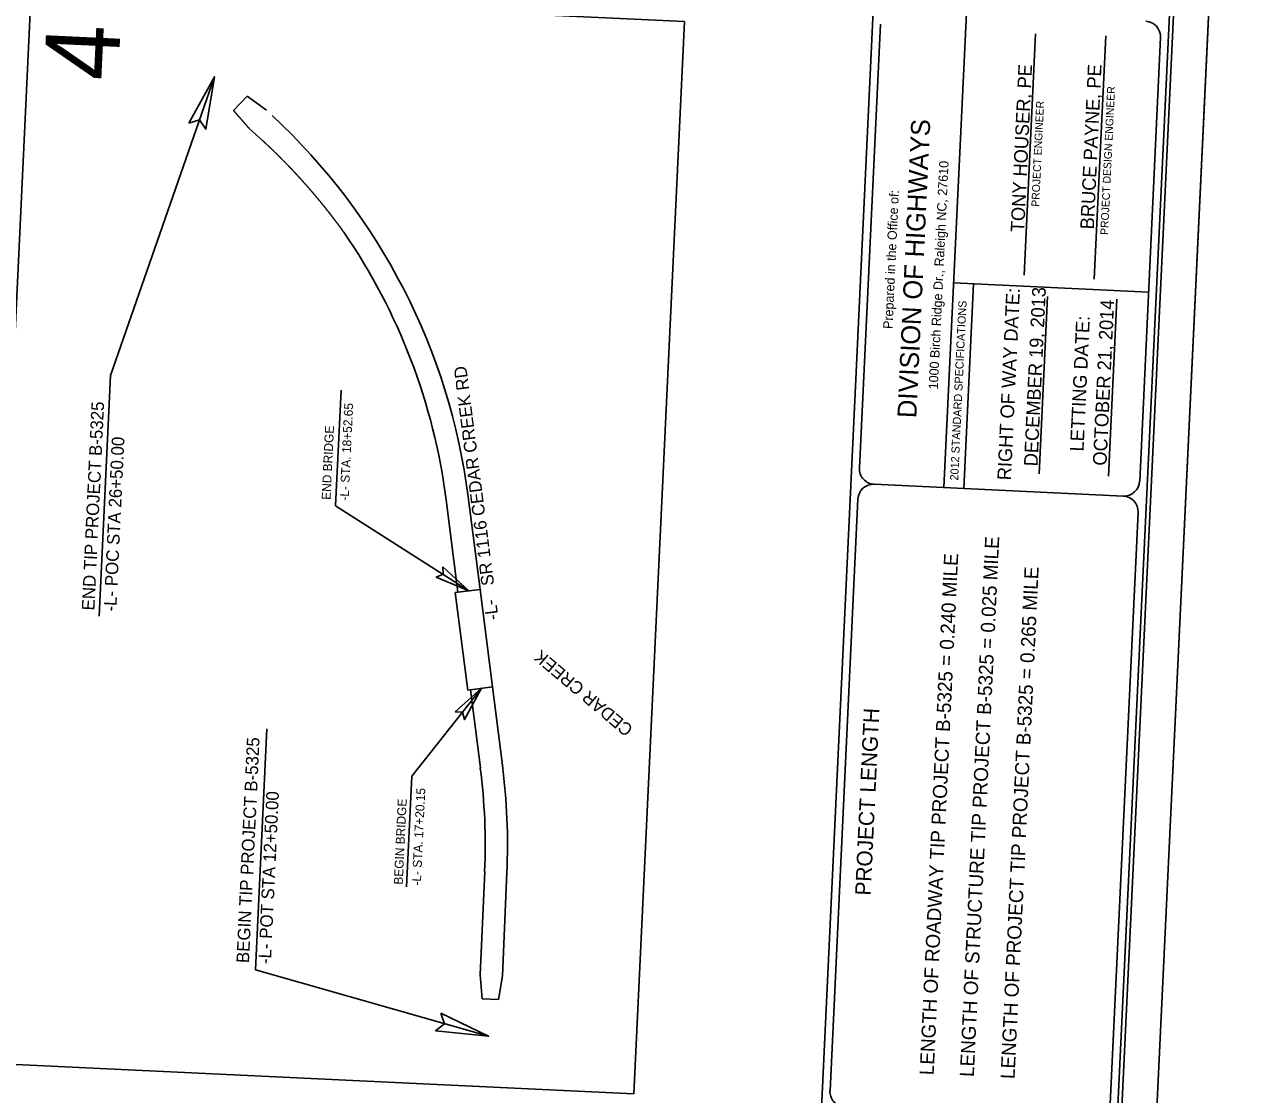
# Model space of a CAD drawing. Extents: x 2166609 to 2169084, y 841593 to 845234.
# Drawn here: x 2167447 to 2169084, y 842808 to 844250 of the extents above; entities that cross this region are included whole.
import ezdxf

# ---------------------------------------------------------------- set-up
doc = ezdxf.new("R2010")
doc.units = 0
for name, color, linetype in [('Default', 7, 'Continuous'), ('Prop Roadway Bridge', 7, 'Continuous'), ('Prop Shade Medium', 7, 'Continuous'), ('Sheet Cutting Line CELL', 7, 'Continuous'), ('Sheet Data Field CELL', 7, 'Continuous'), ('Sheet Plan CELL', 7, 'Continuous'), ('Sheet Plot Border Inside CELL', 7, 'Continuous'), ('Sheet Plot Border Outside CELL', 7, 'Continuous'), ('Sheet Title CELL', 7, 'Continuous'), ('Typical Terminator CELL', 7, 'Continuous')]:
    doc.layers.add(name, color=color, linetype=linetype)

# ---------------------------------------------------------------- blocks, each defined once
blk = doc.blocks.new('TERMINATOR')
at = {"layer": 'Typical Terminator CELL'}
blk.add_lwpolyline([(-0.469, 0.081), (0, 0), (-0.471, -0.083), (-0.411, 0)], close=True, dxfattribs=at)

msp = doc.modelspace()

# ---------------------------------------------------------------- linework, layer by layer
at = {"layer": 'Default'}
for p, q in [((2167563.4, 843776.9), (2167703.5, 844179.7)), ((2167548.1, 843452.8), (2167563.4, 843776.9)), ((2167759, 842976.1), (2167774.4, 843300.8)), ((2168072.9, 842886.8), (2167759, 842976.1))]:
    msp.add_line(p, q, dxfattribs=at)
for points in [[(2167874.2, 843757.5), (2167866.8, 843601.5), (2168046.5, 843487)], [(2168063.3, 843355.6), (2167969.5, 843237.1), (2167962.4, 843088)]]:
    msp.add_lwpolyline(points, dxfattribs=at)
at = {"layer": 'Prop Roadway Bridge'}
for p, q in [((2168028.1, 843484.7), (2168061.4, 843488.9)), ((2168044.9, 843353.2), (2168028.1, 843484.7)), ((2168078.1, 843357.5), (2168061.4, 843488.9)), ((2168044.9, 843353.2), (2168078.1, 843357.5))]:
    msp.add_line(p, q, dxfattribs=at)
at = {"layer": 'Prop Shade Medium'}
for p, q in [((2167729.4, 844134.1), (2167747.5, 844153.5)), ((2167747.5, 844153.5), (2167773.8, 844134.4)), ((2167768.4, 844093.7), (2167750.5, 844109.8)), ((2168031.6, 843485.1), (2168015.7, 843609.7)), ((2168045.5, 843613.5), (2168061.4, 843488.9)), ((2168028.1, 843484.7), (2168044.9, 843353.2)), ((2168061.4, 843488.9), (2168031.6, 843485.1)), ((2168078.1, 843357.5), (2168061.4, 843488.9)), ((2168044.9, 843353.2), (2168048.4, 843353.7)), ((2168048.4, 843353.7), (2168078.1, 843357.5)), ((2168048.4, 843353.7), (2168078.1, 843357.5)), ((2168078.1, 843357.5), (2168048.4, 843353.7)), ((2168048.4, 843353.7), (2168061.9, 843248.3)), ((2168048.4, 843353.7), (2168061.9, 843248.3)), ((2168091.6, 843252.1), (2168078.1, 843357.5)), ((2168091.6, 843252.1), (2168078.1, 843357.5)), ((2168067.7, 843108.7), (2168061.5, 842969.4)), ((2168067.7, 843108.7), (2168061.5, 842969.4)), ((2168091.5, 842968.1), (2168097.6, 843107.4)), ((2168091.5, 842968.1), (2168097.6, 843107.4)), ((2168061.5, 842969.4), (2168064.1, 842937.2)), ((2168061.5, 842969.4), (2168064.1, 842937.2)), ((2168086.1, 842936.3), (2168091.5, 842968.1)), ((2168086.1, 842936.3), (2168091.5, 842968.1)), ((2168064.1, 842937.2), (2168086.1, 842936.3)), ((2168064.1, 842937.2), (2168086.1, 842936.3))]:
    msp.add_line(p, q, dxfattribs=at)
msp.add_lwpolyline([(2168061.4, 843488.9), (2168031.6, 843485.1), (2168028.1, 843484.7)], dxfattribs=at)
for centre, radius, start, end in [((2167204.3, 843506), 848, 7.279, 47.1092), ((2167204.3, 843506), 818, 7.279, 34.5717), ((2167250.4, 843144.6), 818, 357.4856, 7.279), ((2167250.4, 843144.6), 818, 357.4856, 7.279), ((2167250.4, 843144.6), 848, 357.4856, 7.279), ((2167250.4, 843144.6), 848, 357.4856, 7.279)]:
    msp.add_arc(centre, radius, start, end, dxfattribs=at)
for points in [[(2167750.5, 844109.8), (2167750.2, 844110.1), (2167750, 844110.5), (2167749.7, 844110.8), (2167749.4, 844111.1), (2167749.1, 844111.5), (2167748.8, 844111.8), (2167748.5, 844112.1), (2167748.2, 844112.4), (2167748, 844112.8), (2167747.7, 844113.1), (2167747.4, 844113.4), (2167747.1, 844113.8), (2167746.8, 844114.1), (2167746.5, 844114.4), (2167746.2, 844114.7), (2167746, 844115.1), (2167745.7, 844115.4), (2167745.4, 844115.7), (2167745.1, 844116.1), (2167744.8, 844116.4), (2167744.5, 844116.7), (2167744.2, 844117), (2167744, 844117.4), (2167743.7, 844117.7), (2167743.4, 844118), (2167743.1, 844118.4), (2167742.8, 844118.7), (2167742.5, 844119), (2167742.2, 844119.3), (2167742, 844119.7), (2167741.7, 844120), (2167741.4, 844120.3), (2167741.1, 844120.7), (2167740.8, 844121), (2167740.5, 844121.3), (2167740.2, 844121.6), (2167740, 844122), (2167739.7, 844122.3), (2167739.4, 844122.6), (2167739.1, 844122.9), (2167738.8, 844123.3), (2167738.5, 844123.6), (2167738.2, 844123.9), (2167738, 844124.3), (2167737.7, 844124.6), (2167737.4, 844124.9), (2167737.1, 844125.2), (2167736.8, 844125.6), (2167736.5, 844125.9), (2167736.2, 844126.2), (2167736, 844126.6), (2167735.7, 844126.9), (2167735.4, 844127.2), (2167735.1, 844127.5), (2167734.8, 844127.9), (2167734.5, 844128.2), (2167734.2, 844128.5), (2167734, 844128.9), (2167733.7, 844129.2), (2167733.4, 844129.5), (2167733.1, 844129.8), (2167732.8, 844130.2), (2167732.5, 844130.5), (2167732.2, 844130.8), (2167732, 844131.2), (2167731.7, 844131.5), (2167731.4, 844131.8), (2167731.1, 844132.2), (2167730.8, 844132.5), (2167730.5, 844132.8), (2167730.2, 844133.1), (2167730, 844133.5), (2167729.4, 844134.1)], [(2167807.6, 844055.1), (2167807.1, 844055.6), (2167806.6, 844056.2), (2167806.1, 844056.7), (2167805.5, 844057.2), (2167805, 844057.8), (2167804.5, 844058.3), (2167804, 844058.8), (2167803.5, 844059.4), (2167803, 844059.9), (2167802.5, 844060.5), (2167801.9, 844061), (2167801.4, 844061.5), (2167800.9, 844062.1), (2167800.4, 844062.6), (2167799.9, 844063.1), (2167799.3, 844063.7), (2167798.8, 844064.2), (2167798.3, 844064.7), (2167797.8, 844065.3), (2167797.3, 844065.8), (2167796.7, 844066.3), (2167796.2, 844066.8), (2167795.7, 844067.4), (2167795.2, 844067.9), (2167794.6, 844068.4), (2167794.1, 844069), (2167793.6, 844069.5), (2167793.1, 844070), (2167792.5, 844070.5), (2167792, 844071.1), (2167791.5, 844071.6), (2167791, 844072.1), (2167790.4, 844072.6), (2167789.9, 844073.2), (2167789.4, 844073.7), (2167788.9, 844074.2), (2167788.3, 844074.7), (2167787.8, 844075.3), (2167787.3, 844075.8), (2167786.7, 844076.3), (2167786.2, 844076.8), (2167785.7, 844077.3), (2167785.1, 844077.9), (2167784.6, 844078.4), (2167784.1, 844078.9), (2167783.5, 844079.4), (2167783, 844079.9), (2167782.5, 844080.5), (2167781.9, 844081), (2167781.4, 844081.5), (2167780.9, 844082), (2167780.3, 844082.5), (2167779.8, 844083), (2167779.2, 844083.5), (2167778.7, 844084.1), (2167778.2, 844084.6), (2167777.6, 844085.1), (2167777.1, 844085.6), (2167776.6, 844086.1), (2167776, 844086.6), (2167775.5, 844087.1), (2167774.9, 844087.6), (2167774.4, 844088.2), (2167773.8, 844088.7), (2167773.3, 844089.2), (2167772.8, 844089.7), (2167772.2, 844090.2), (2167771.7, 844090.7), (2167771.1, 844091.2), (2167770.6, 844091.7), (2167770, 844092.2), (2167769.5, 844092.7), (2167768.9, 844093.2), (2167768.4, 844093.7)], [(2167844.2, 844013.8), (2167843.7, 844014.4), (2167843.2, 844015), (2167842.7, 844015.5), (2167842.3, 844016.1), (2167841.8, 844016.7), (2167841.3, 844017.3), (2167840.8, 844017.8), (2167840.3, 844018.4), (2167839.9, 844019), (2167839.4, 844019.5), (2167838.9, 844020.1), (2167838.4, 844020.7), (2167837.9, 844021.2), (2167837.5, 844021.8), (2167837, 844022.4), (2167836.5, 844023), (2167836, 844023.5), (2167835.5, 844024.1), (2167835, 844024.6), (2167834.5, 844025.2), (2167834.1, 844025.8), (2167833.6, 844026.3), (2167833.1, 844026.9), (2167832.6, 844027.5), (2167832.1, 844028), (2167831.6, 844028.6), (2167831.1, 844029.2), (2167830.6, 844029.7), (2167830.2, 844030.3), (2167829.7, 844030.8), (2167829.2, 844031.4), (2167828.7, 844032), (2167828.2, 844032.5), (2167827.7, 844033.1), (2167827.2, 844033.6), (2167826.7, 844034.2), (2167826.2, 844034.8), (2167825.7, 844035.3), (2167825.2, 844035.9), (2167824.7, 844036.4), (2167824.2, 844037), (2167823.7, 844037.5), (2167823.2, 844038.1), (2167822.8, 844038.7), (2167822.3, 844039.2), (2167821.8, 844039.8), (2167821.3, 844040.3), (2167820.8, 844040.9), (2167820.3, 844041.4), (2167819.8, 844042), (2167819.3, 844042.5), (2167818.8, 844043.1), (2167818.3, 844043.6), (2167817.8, 844044.2), (2167817.2, 844044.7), (2167816.7, 844045.3), (2167816.2, 844045.8), (2167815.7, 844046.4), (2167815.2, 844046.9), (2167814.7, 844047.5), (2167814.2, 844048), (2167813.7, 844048.6), (2167813.2, 844049.1), (2167812.7, 844049.7), (2167812.2, 844050.2), (2167811.7, 844050.7), (2167811.2, 844051.3), (2167810.7, 844051.8), (2167810.2, 844052.4), (2167809.6, 844052.9), (2167809.1, 844053.5), (2167808.6, 844054), (2167808.1, 844054.5), (2167807.6, 844055.1)], [(2167877.9, 843970.1), (2167877.5, 843970.7), (2167877, 843971.3), (2167876.6, 843971.9), (2167876.1, 843972.5), (2167875.7, 843973.1), (2167875.3, 843973.8), (2167874.8, 843974.4), (2167874.4, 843975), (2167873.9, 843975.6), (2167873.5, 843976.2), (2167873.1, 843976.8), (2167872.6, 843977.4), (2167872.2, 843978), (2167871.7, 843978.6), (2167871.3, 843979.2), (2167870.8, 843979.8), (2167870.4, 843980.4), (2167870, 843981), (2167869.5, 843981.6), (2167869.1, 843982.2), (2167868.6, 843982.8), (2167868.2, 843983.4), (2167867.7, 843984), (2167867.3, 843984.5), (2167866.8, 843985.1), (2167866.4, 843985.7), (2167865.9, 843986.3), (2167865.5, 843986.9), (2167865, 843987.5), (2167864.6, 843988.1), (2167864.1, 843988.7), (2167863.7, 843989.3), (2167863.2, 843989.9), (2167862.8, 843990.5), (2167862.3, 843991.1), (2167861.8, 843991.7), (2167861.4, 843992.3), (2167860.9, 843992.9), (2167860.5, 843993.4), (2167860, 843994), (2167859.6, 843994.6), (2167859.1, 843995.2), (2167858.6, 843995.8), (2167858.2, 843996.4), (2167857.7, 843997), (2167857.3, 843997.6), (2167856.8, 843998.1), (2167856.3, 843998.7), (2167855.9, 843999.3), (2167855.4, 843999.9), (2167855, 844000.5), (2167854.5, 844001.1), (2167854, 844001.7), (2167853.6, 844002.2), (2167853.1, 844002.8), (2167852.6, 844003.4), (2167852.2, 844004), (2167851.7, 844004.6), (2167851.2, 844005.1), (2167850.8, 844005.7), (2167850.3, 844006.3), (2167849.8, 844006.9), (2167849.4, 844007.5), (2167848.9, 844008), (2167848.4, 844008.6), (2167847.9, 844009.2), (2167847.5, 844009.8), (2167847, 844010.4), (2167846.5, 844010.9), (2167846.1, 844011.5), (2167845.6, 844012.1), (2167845.1, 844012.7), (2167844.6, 844013.2), (2167844.2, 844013.8)]]:
    msp.add_spline(points, degree=3, dxfattribs=at)
at = {"layer": 'Sheet Cutting Line CELL'}
msp.add_line((2168916.8, 841592.8), (2169083.6, 845125.2), dxfattribs=at)
at = {"layer": 'Sheet Plan CELL'}
msp.add_lwpolyline([(2167388.5, 842851), (2167456.7, 844295.5), (2168336.9, 844253.9), (2168268.7, 842809.4)], close=True, dxfattribs=at)
at = {"layer": 'Sheet Plot Border Inside CELL'}
msp.add_lwpolyline([(2168871, 841622.3), (2169036.1, 845118), (2166822.9, 845222.5), (2166657.8, 841726.8)], close=True, dxfattribs=at)
at = {"layer": 'Sheet Plot Border Outside CELL'}
msp.add_lwpolyline([(2166776.2, 845234.2), (2166609.4, 841701.7), (2168916.8, 841592.8), (2169083.6, 845125.2)], close=True, dxfattribs=at)
at = {"layer": 'Sheet Title CELL'}
for p, q in [((2168488.8, 842100.7), (2168629.5, 845079.4)), ((2168716.7, 844265.9), (2168686.4, 843626.1)), ((2168572.6, 843652.5), (2168600.8, 844250.3)), ((2168794.5, 843912.1), (2168809.9, 844237.5)), ((2168888.9, 843906.9), (2168904.4, 844234.6)), ((2168699.5, 843902), (2168962.2, 843889.6)), ((2168726.2, 843900.8), (2168713.2, 843624.8)), ((2168826, 843883.5), (2168814.7, 843644.8)), ((2168919.6, 843879.9), (2168908.3, 843641.3)), ((2168722.5, 843821.3), (2168722.5, 843821.3)), ((2168820.4, 843764.1), (2168820.4, 843764.1)), ((2168592.6, 843630.5), (2168928.2, 843614.7)), ((2168533, 842813.4), (2168570.6, 843610.5))]:
    msp.add_line(p, q, dxfattribs=at)
for points in [[(2168881.9, 841966.5), (2169028.5, 845071.1)], [(2168950.2, 843634.7), (2168978.4, 844232.5)], [(2168910.6, 842795.6), (2168948.2, 843592.7)]]:
    msp.add_lwpolyline(points, dxfattribs=at)
for centre, start, end in [((2168957.3, 844233.5), 357.2959, 87.2959), ((2168593.5, 843651.5), 177.2959, 267.2959), ((2168591.5, 843609.6), 87.2959, 177.2959), ((2168929.1, 843635.7), 267.2959, 357.2959), ((2168927.1, 843593.7), 357.2959, 87.2959), ((2168553.8, 842812.5), 177.2959, 267.2959)]:
    msp.add_arc(centre, 21, start, end, dxfattribs=at)

# ---------------------------------------------------------------- block references
at = {"layer": 'Default'}
for p, xscale, yscale, rotation in [((2167703.5, 844179.7), 149.99999999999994, 149.99999999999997, 70.82132466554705), ((2168046.5, 843487), 99.99999999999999, 99.99999999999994, -32.66673608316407), ((2168063.3, 843355.6), 100, 99.99999999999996, 51.64039721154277), ((2168072.9, 842886.8), 150, 149.99999999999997, -15.88372985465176)]:
    msp.add_blockref('TERMINATOR', p, dxfattribs=dict(at, xscale=xscale, yscale=yscale, rotation=rotation))

# ---------------------------------------------------------------- texts
for s, height, rotation, p in [('4', 100, 87.2959, (2167573.7, 844173.4)), ('-L-   SR 1116 CEDAR CREEK RD', 17, 97.279, (2168086.5, 843448.6)), ('END TIP PROJECT B-5325', 17, 87.2959, (2167541.8, 843460.2)), ('-L- STA. 18+52.65', 12, 87.2959, (2167884.4, 843608.3)), ('END BRIDGE', 12, 87.2959, (2167860, 843609.4)), ('-L- POC STA 26+50.00', 17, 87.2959, (2167571.3, 843458.8)), ('CEDAR CREEK', 17, 139.8346, (2168268.9, 843302.4)), ('BEGIN TIP PROJECT B-5325', 17, 87.2959, (2167750.1, 842985.1)), ('-L- POT STA 12+50.00', 17, 87.2959, (2167779.6, 842983.7)), ('-L- STA. 17+20.15', 12, 87.2959, (2167981.6, 843089.6)), ('BEGIN BRIDGE', 12, 87.2959, (2167957.2, 843090.8))]:
    msp.add_text(s, height=height, rotation=rotation, dxfattribs=at).set_placement(p)
at = {"layer": 'Sheet Data Field CELL'}
for s, height, p in [('TONY HOUSER, PE', 18.375, (2168794.6, 843969.8)), ('BRUCE PAYNE, PE', 18.375, (2168888.4, 843973.7)), ('DECEMBER 19, 2013', 18.375, (2168812.5, 843654.4)), ('OCTOBER 21, 2014', 18.375, (2168905.4, 843655.3)), ('LENGTH OF STRUCTURE TIP PROJECT B-5325 = 0.025 MILE', 19, (2168726.7, 842831.6)), ('LENGTH OF ROADWAY TIP PROJECT B-5325 = 0.240 MILE', 19, (2168672.6, 842834)), ('LENGTH OF PROJECT TIP PROJECT B-5325 = 0.265 MILE', 19, (2168781.6, 842828.8))]:
    msp.add_text(s, height=height, rotation=87.2959, dxfattribs=at).set_placement(p)
at = {"layer": 'Sheet Title CELL'}
for s, height, p in [('PROJECT DESIGN ENGINEER', 10.499, (2168907.6, 843966.3)), ('PROJECT ENGINEER', 10.499, (2168814.7, 844004.3)), ('DIVISION OF HIGHWAYS', 25.593, (2168649.2, 843719.3)), ('1000 Birch Ridge Dr., Raleigh NC, 27610', 12.6, (2168678.3, 843758.2)), ('Prepared in the Office of:', 12.599, (2168617.1, 843839.6)), ('RIGHT OF WAY DATE: ', 18.375, (2168776.7, 843635.6)), ('2012 STANDARD SPECIFICATIONS', 10.92, (2168705.6, 843635.4)), ('LETTING DATE:', 18.375, (2168874.5, 843674.4)), ('PROJECT LENGTH', 20.999, (2168587.7, 843076))]:
    msp.add_text(s, height=height, rotation=87.2959, dxfattribs=at).set_placement(p)

doc.saveas('drawing.dxf')
